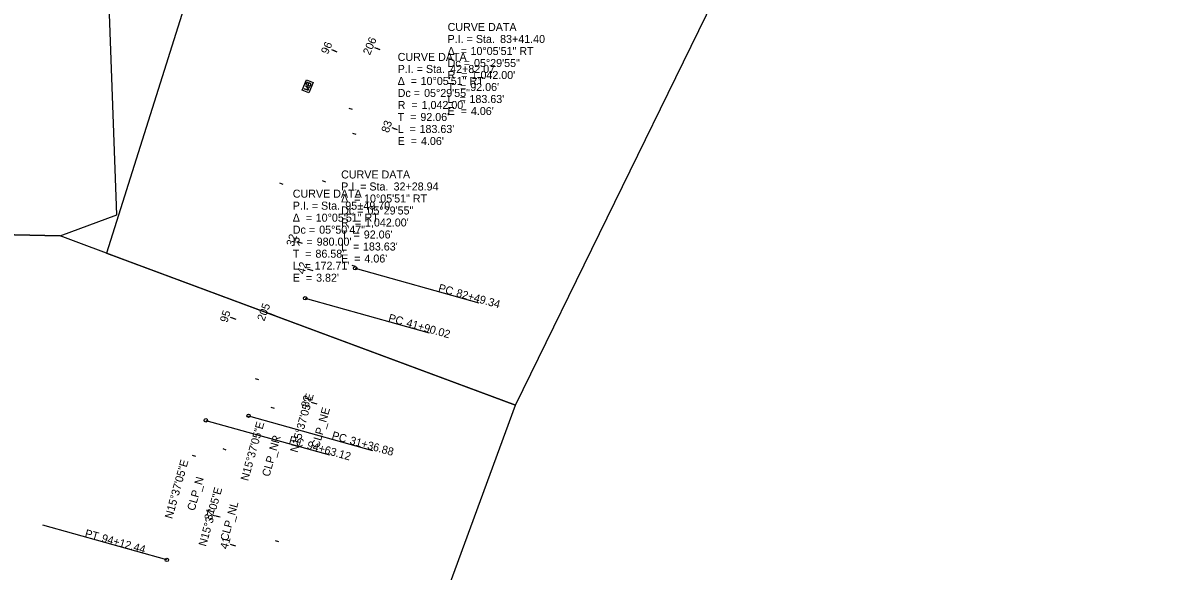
# Model space of a CAD drawing. Extents: x 1564517 to 1565226, y 635740 to 637455.
# Drawn here: x 1564828.9 to 1565225.9, y 636631.2 to 636823.1 of the extents above; entities that cross this region are included whole.
import ezdxf

# ---------------------------------------------------------------- set-up
doc = ezdxf.new("R2010")
doc.units = 0
for name, color, linetype in [('GK_Drainage_Nodes', 7, 'Continuous'), ('RD_P_Cells', 7, 'Continuous'), ('SC_Scratch10', 7, 'Continuous'), ('TX_P_1000', 7, 'Continuous'), ('UT_P_Water', 7, 'Continuous'), ('UT_P_Water_Cells', 7, 'Continuous'), ('UT_X_Electric', 7, 'Continuous'), ('UT_X_Sanitary_Pressure_Line', 7, 'Continuous'), ('UT_X_Water_Cells', 7, 'Continuous')]:
    doc.layers.add(name, color=color, linetype=linetype)

msp = doc.modelspace()

# ---------------------------------------------------------------- linework, layer by layer
at = {"layer": 'RD_P_Cells'}
msp.add_line((1564928.62, 636800.87), (1564928.62, 636800.87), dxfattribs=at)
msp.add_lwpolyline([(1564926.73, 636799.48), (1564928.25, 636803.19), (1564930.51, 636802.26), (1564928.99, 636798.56)], close=True, dxfattribs=at)
for points in [[(1564928.87, 636799.37), (1564927.39, 636799.98), (1564929.09, 636799.91), (1564927.82, 636801.03), (1564929.3, 636800.42)], [(1564928.94, 636801.84), (1564928.91, 636801.93), (1564928.89, 636801.98), (1564928.86, 636802.01), (1564928.84, 636802.03), (1564928.81, 636802.08), (1564928.78, 636802.1), (1564928.7, 636802.16), (1564928.67, 636802.17), (1564928.62, 636802.19), (1564928.55, 636802.21), (1564928.48, 636802.21), (1564928.42, 636802.19), (1564928.35, 636802.16), (1564928.31, 636802.12), (1564928.28, 636802.1), (1564928.24, 636802.05), (1564928, 636801.48), (1564929.48, 636800.87), (1564929.75, 636801.52), (1564929.73, 636801.62), (1564929.7, 636801.71), (1564929.63, 636801.81), (1564929.54, 636801.88), (1564929.44, 636801.94), (1564929.37, 636801.97), (1564929.29, 636801.97), (1564929.17, 636801.97), (1564929.08, 636801.94), (1564928.94, 636801.84), (1564928.68, 636801.2)]]:
    msp.add_lwpolyline(points, dxfattribs=at)
at = {"layer": 'TX_P_1000'}
for p, q in [((1564927.77, 636726.75), (1564971.11, 636714.64)), ((1564907.97, 636685.64), (1564951.31, 636673.53))]:
    msp.add_line(p, q, dxfattribs=at)
at = {"layer": 'UT_P_Water_Cells'}
for p, q in [((1564938.91, 636812.87), (1564937.81, 636813.35)), ((1564954.03, 636813.6), (1564952.93, 636814.07)), ((1564960.06, 636785.67), (1564958.92, 636786.05)), ((1564926.8, 636745.88), (1564925.66, 636746.27)), ((1564930.51, 636736.36), (1564929.35, 636736.69)), ((1564945.24, 636737.24), (1564988.58, 636725.12)), ((1564927.77, 636726.75), (1564971.11, 636714.64)), ((1564903.58, 636719.36), (1564901.68, 636719.97)), ((1564916.98, 636720.72), (1564915.11, 636721.42)), ((1564931.95, 636689.72), (1564930.8, 636690.04)), ((1564892.99, 636684.04), (1564936.33, 636671.92)), ((1564907.97, 636685.64), (1564951.31, 636673.53)), ((1564898.04, 636650.12), (1564896.89, 636650.45)), ((1564879.34, 636635.23), (1564836, 636647.34)), ((1564903.54, 636640.06), (1564902.38, 636640.38))]:
    msp.add_line(p, q, dxfattribs=at)
for centre in [(1564945.24, 636737.24), (1564927.77, 636726.75), (1564892.99, 636684.04), (1564907.97, 636685.64), (1564879.34, 636635.23)]:
    msp.add_circle(centre, 0.6, dxfattribs=at)
at = {"layer": 'UT_X_Electric'}
for points in [[(1564682.06, 636752.05), (1564842.01, 636748.56), (1564861.83, 636755.87), (1564842.73, 637279.63), (1564517.04, 637293.63), (1564662.12, 636876.82)], [(1564858.24, 636742.53), (1565001.39, 636689.39), (1565225.94, 637148.15), (1565017.94, 637248.32)], [(1564685.49, 636222.38), (1564930.72, 636197.15), (1564955.53, 636388.56), (1565013.42, 636482), (1565045.03, 636594.7), (1564968.04, 636598.47), (1565001.39, 636689.39), (1564864.83, 636740.08), (1564842.01, 636748.56), (1564682.06, 636752.05), (1564649.71, 636425.72), (1564708.41, 636418.15)]]:
    msp.add_lwpolyline(points, close=True, dxfattribs=at)
at = {"layer": 'UT_X_Sanitary_Pressure_Line'}
for p, q in [((1564945.24, 636737.24), (1564988.58, 636725.12)), ((1564927.77, 636726.75), (1564971.11, 636714.64)), ((1564903.58, 636719.36), (1564902.44, 636719.73)), ((1564916.98, 636720.72), (1564915.86, 636721.14)), ((1564892.99, 636684.04), (1564936.33, 636671.92)), ((1564907.97, 636685.64), (1564951.31, 636673.53)), ((1564879.34, 636635.23), (1564836, 636647.34))]:
    msp.add_line(p, q, dxfattribs=at)
for centre in [(1564945.24, 636737.24), (1564927.77, 636726.75), (1564892.99, 636684.04), (1564907.97, 636685.64), (1564879.34, 636635.23)]:
    msp.add_circle(centre, 0.6, dxfattribs=at)
at = {"layer": 'UT_X_Water_Cells'}
for p, q in [((1564938.91, 636812.87), (1564937.08, 636813.67)), ((1564954.03, 636813.6), (1564952.19, 636814.38)), ((1564944.27, 636792.72), (1564943.16, 636793.17)), ((1564945.57, 636784.03), (1564944.44, 636784.42)), ((1564960.06, 636785.67), (1564958.16, 636786.31)), ((1564934.95, 636767.38), (1564933.83, 636767.83)), ((1564920.05, 636766.57), (1564918.93, 636766.99)), ((1564926.8, 636745.88), (1564924.91, 636746.53)), ((1564930.51, 636736.36), (1564928.58, 636736.91)), ((1564945.42, 636737.87), (1564944.26, 636738.2)), ((1564903.58, 636719.36), (1564901.68, 636719.97)), ((1564916.98, 636720.72), (1564915.11, 636721.42)), ((1564911.58, 636698.25), (1564910.43, 636698.59)), ((1564917, 636688.22), (1564915.84, 636688.54)), ((1564931.95, 636689.72), (1564930.03, 636690.26)), ((1564900.15, 636673.64), (1564899.01, 636674.04)), ((1564889.46, 636671.4), (1564888.3, 636671.73)), ((1564898.04, 636650.12), (1564896.12, 636650.66)), ((1564903.54, 636640.06), (1564901.61, 636640.6)), ((1564918.49, 636641.56), (1564917.34, 636641.89))]:
    msp.add_line(p, q, dxfattribs=at)
for centre in [(1564927.77, 636726.75), (1564907.97, 636685.64)]:
    msp.add_circle(centre, 0.6, dxfattribs=at)

# ---------------------------------------------------------------- texts
at = {"layer": 'GK_Drainage_Nodes'}
for s, p in [('CURVE DATA', (1564977.6, 636820.23)), ('P.I. = Sta. ', (1564977.6, 636816.03)), ('83+41.40', (1564995.97, 636816.03)), ('CURVE DATA', (1564960.13, 636809.75)), ('Δ  = ', (1564977.6, 636811.83)), ('10°05\'51" RT', (1564985.62, 636811.83)), ('P.I. = Sta. ', (1564960.13, 636805.55)), ('Dc = ', (1564977.6, 636807.63)), ('42+82.07', (1564978.5, 636805.55)), ('05°29\'55"', (1564986.84, 636807.63)), ('Δ  = ', (1564960.13, 636801.35)), ('10°05\'51" RT', (1564968.16, 636801.35)), ('R  = ', (1564977.6, 636803.43)), ("1,042.00'", (1564985.97, 636803.43)), ('Dc = ', (1564960.13, 636797.15)), ('05°29\'55"', (1564969.37, 636797.15)), ('T  = ', (1564977.6, 636799.23)), ("92.06'", (1564985.53, 636799.23)), ('R  = ', (1564960.13, 636792.95)), ("1,042.00'", (1564968.5, 636792.95)), ('L  = ', (1564977.6, 636795.03)), ("183.63'", (1564985.25, 636795.03)), ('T  = ', (1564960.13, 636788.75)), ("92.06'", (1564968.07, 636788.75)), ('E  = ', (1564977.6, 636790.83)), ("4.06'", (1564985.75, 636790.83)), ('L  = ', (1564960.13, 636784.55)), ("183.63'", (1564967.78, 636784.55)), ("4.06'", (1564968.29, 636780.35)), ('E  = ', (1564960.13, 636780.35)), ('CURVE DATA', (1564940.34, 636768.64)), ('CURVE DATA', (1564923.42, 636761.93)), ('P.I. = Sta. ', (1564940.34, 636764.44)), ('32+28.94', (1564958.7, 636764.44)), ('P.I. = Sta. ', (1564923.42, 636757.73)), ('Δ  = ', (1564940.34, 636760.24)), ('95+49.70', (1564941.79, 636757.73)), ('10°05\'51" RT', (1564948.36, 636760.24)), ('Δ  = ', (1564923.42, 636753.53)), ('10°05\'51" RT', (1564931.45, 636753.53)), ('Dc = ', (1564940.34, 636756.04)), ('05°29\'55"', (1564949.57, 636756.04)), ('Dc = ', (1564923.42, 636749.33)), ('05°50\'47"', (1564932.66, 636749.33)), ('R  = ', (1564940.34, 636751.84)), ("1,042.00'", (1564948.7, 636751.84)), ('R  = ', (1564923.42, 636745.13)), ("980.00'", (1564931.79, 636745.13)), ('T  = ', (1564940.34, 636747.64)), ("92.06'", (1564948.27, 636747.64)), ('T  = ', (1564923.42, 636740.93)), ("86.58'", (1564931.36, 636740.93)), ('L  = ', (1564940.34, 636743.44)), ("183.63'", (1564947.98, 636743.44)), ('L  = ', (1564923.42, 636736.73)), ("172.71'", (1564931.07, 636736.73)), ('E  = ', (1564940.34, 636739.24)), ("4.06'", (1564948.49, 636739.24)), ('E  = ', (1564923.42, 636732.53)), ("3.82'", (1564931.58, 636732.53))]:
    msp.add_text(s, height=2.8, dxfattribs=at).set_placement(p)
for s, p in [('N15°37\'05"E', (1564925.09, 636672.58)), ('CLP_NE', (1564932.57, 636674.1)), ('N15°37\'05"E', (1564907.78, 636662.66)), ('CLP_NR', (1564915.25, 636664.15)), ('N15°37\'05"E', (1564881.23, 636649.4)), ('CLP_N', (1564889.07, 636652.21)), ('N15°37\'05"E', (1564893.06, 636639.74)), ('CLP_NL', (1564900.65, 636641.62))]:
    msp.add_text(s, height=2.8, rotation=74.3818, dxfattribs=at).set_placement(p)
at = {"layer": 'SC_Scratch10'}
for s, p in [('CURVE DATA', (1564977.6, 636820.23)), ('P.I. = Sta. ', (1564977.6, 636816.03)), ('83+41.40', (1564995.97, 636816.03)), ('CURVE DATA', (1564960.13, 636809.75)), ('Δ  = ', (1564977.6, 636811.83)), ('10°05\'51" RT', (1564985.62, 636811.83)), ('P.I. = Sta. ', (1564960.13, 636805.55)), ('Dc = ', (1564977.6, 636807.63)), ('42+82.07', (1564978.5, 636805.55)), ('05°29\'55"', (1564986.84, 636807.63)), ('Δ  = ', (1564960.13, 636801.35)), ('10°05\'51" RT', (1564968.16, 636801.35)), ('R  = ', (1564977.6, 636803.43)), ("1,042.00'", (1564985.97, 636803.43)), ('Dc = ', (1564960.13, 636797.15)), ('05°29\'55"', (1564969.37, 636797.15)), ('T  = ', (1564977.6, 636799.23)), ("92.06'", (1564985.53, 636799.23)), ('R  = ', (1564960.13, 636792.95)), ("1,042.00'", (1564968.5, 636792.95)), ('L  = ', (1564977.6, 636795.03)), ("183.63'", (1564985.25, 636795.03)), ('T  = ', (1564960.13, 636788.75)), ("92.06'", (1564968.07, 636788.75)), ('E  = ', (1564977.6, 636790.83)), ("4.06'", (1564985.75, 636790.83)), ('L  = ', (1564960.13, 636784.55)), ("183.63'", (1564967.78, 636784.55)), ("4.06'", (1564968.29, 636780.35)), ('E  = ', (1564960.13, 636780.35)), ('CURVE DATA', (1564940.34, 636768.64)), ('CURVE DATA', (1564923.42, 636761.93)), ('P.I. = Sta. ', (1564940.34, 636764.44)), ('32+28.94', (1564958.7, 636764.44)), ('P.I. = Sta. ', (1564923.42, 636757.73)), ('Δ  = ', (1564940.34, 636760.24)), ('95+49.70', (1564941.79, 636757.73)), ('10°05\'51" RT', (1564948.36, 636760.24)), ('Δ  = ', (1564923.42, 636753.53)), ('10°05\'51" RT', (1564931.45, 636753.53)), ('Dc = ', (1564940.34, 636756.04)), ('05°29\'55"', (1564949.57, 636756.04)), ('Dc = ', (1564923.42, 636749.33)), ('05°50\'47"', (1564932.66, 636749.33)), ('R  = ', (1564940.34, 636751.84)), ("1,042.00'", (1564948.7, 636751.84)), ('R  = ', (1564923.42, 636745.13)), ("980.00'", (1564931.79, 636745.13)), ('T  = ', (1564940.34, 636747.64)), ("92.06'", (1564948.27, 636747.64)), ('T  = ', (1564923.42, 636740.93)), ("86.58'", (1564931.36, 636740.93)), ('L  = ', (1564940.34, 636743.44)), ("183.63'", (1564947.98, 636743.44)), ('L  = ', (1564923.42, 636736.73)), ("172.71'", (1564931.07, 636736.73)), ('E  = ', (1564940.34, 636739.24)), ("4.06'", (1564948.49, 636739.24)), ('E  = ', (1564923.42, 636732.53)), ("3.82'", (1564931.58, 636732.53))]:
    msp.add_text(s, height=2.8, dxfattribs=at).set_placement(p)
for s, p in [('N15°37\'05"E', (1564925.09, 636672.58)), ('CLP_NE', (1564932.57, 636674.1)), ('N15°37\'05"E', (1564907.78, 636662.66)), ('CLP_NR', (1564915.25, 636664.15)), ('N15°37\'05"E', (1564881.23, 636649.4)), ('CLP_N', (1564889.07, 636652.21)), ('N15°37\'05"E', (1564893.06, 636639.74)), ('CLP_NL', (1564900.65, 636641.62))]:
    msp.add_text(s, height=2.8, rotation=74.3818, dxfattribs=at).set_placement(p)
at = {"layer": 'UT_P_Water'}
for s, p in [('CURVE DATA', (1564977.6, 636820.23)), ('P.I. = Sta. ', (1564977.6, 636816.03)), ('83+41.40', (1564995.97, 636816.03)), ('CURVE DATA', (1564960.13, 636809.75)), ('Δ  = ', (1564977.6, 636811.83)), ('10°05\'51" RT', (1564985.62, 636811.83)), ('P.I. = Sta. ', (1564960.13, 636805.55)), ('Dc = ', (1564977.6, 636807.63)), ('42+82.07', (1564978.5, 636805.55)), ('05°29\'55"', (1564986.84, 636807.63)), ('Δ  = ', (1564960.13, 636801.35)), ('10°05\'51" RT', (1564968.16, 636801.35)), ('R  = ', (1564977.6, 636803.43)), ("1,042.00'", (1564985.97, 636803.43)), ('Dc = ', (1564960.13, 636797.15)), ('05°29\'55"', (1564969.37, 636797.15)), ('T  = ', (1564977.6, 636799.23)), ("92.06'", (1564985.53, 636799.23)), ('R  = ', (1564960.13, 636792.95)), ("1,042.00'", (1564968.5, 636792.95)), ('L  = ', (1564977.6, 636795.03)), ("183.63'", (1564985.25, 636795.03)), ('T  = ', (1564960.13, 636788.75)), ("92.06'", (1564968.07, 636788.75)), ('E  = ', (1564977.6, 636790.83)), ("4.06'", (1564985.75, 636790.83)), ('L  = ', (1564960.13, 636784.55)), ("183.63'", (1564967.78, 636784.55)), ("4.06'", (1564968.29, 636780.35)), ('E  = ', (1564960.13, 636780.35)), ('CURVE DATA', (1564940.34, 636768.64)), ('CURVE DATA', (1564923.42, 636761.93)), ('P.I. = Sta. ', (1564940.34, 636764.44)), ('32+28.94', (1564958.7, 636764.44)), ('P.I. = Sta. ', (1564923.42, 636757.73)), ('Δ  = ', (1564940.34, 636760.24)), ('95+49.70', (1564941.79, 636757.73)), ('10°05\'51" RT', (1564948.36, 636760.24)), ('Δ  = ', (1564923.42, 636753.53)), ('10°05\'51" RT', (1564931.45, 636753.53)), ('Dc = ', (1564940.34, 636756.04)), ('05°29\'55"', (1564949.57, 636756.04)), ('Dc = ', (1564923.42, 636749.33)), ('05°50\'47"', (1564932.66, 636749.33)), ('R  = ', (1564940.34, 636751.84)), ("1,042.00'", (1564948.7, 636751.84)), ('R  = ', (1564923.42, 636745.13)), ("980.00'", (1564931.79, 636745.13)), ('T  = ', (1564940.34, 636747.64)), ("92.06'", (1564948.27, 636747.64)), ('T  = ', (1564923.42, 636740.93)), ("86.58'", (1564931.36, 636740.93)), ('L  = ', (1564940.34, 636743.44)), ("183.63'", (1564947.98, 636743.44)), ('L  = ', (1564923.42, 636736.73)), ("172.71'", (1564931.07, 636736.73)), ('E  = ', (1564940.34, 636739.24)), ("4.06'", (1564948.49, 636739.24)), ('E  = ', (1564923.42, 636732.53)), ("3.82'", (1564931.58, 636732.53))]:
    msp.add_text(s, height=2.8, dxfattribs=at).set_placement(p)
for s, p in [('N15°37\'05"E', (1564925.09, 636672.58)), ('CLP_NE', (1564932.57, 636674.1)), ('N15°37\'05"E', (1564907.78, 636662.66)), ('CLP_NR', (1564915.25, 636664.15)), ('N15°37\'05"E', (1564881.23, 636649.4)), ('CLP_N', (1564889.07, 636652.21)), ('N15°37\'05"E', (1564893.06, 636639.74)), ('CLP_NL', (1564900.65, 636641.62))]:
    msp.add_text(s, height=2.8, rotation=74.3818, dxfattribs=at).set_placement(p)
at = {"layer": 'UT_P_Water_Cells'}
for s, rotation, p in [('PC', 344.3818, (1564974.13, 636729.16)), ('82+49.34', 344.3818, (1564980.41, 636727.4)), ('205', 69.633, (1564913.45, 636718.52)), ('95', 72.2255, (1564900.48, 636718.04)), ('PC', 344.3818, (1564956.66, 636718.68)), ('41+90.02', 344.3818, (1564962.94, 636716.92)), ('PC', 344.3818, (1564936.86, 636677.57)), ('PC', 344.3818, (1564921.88, 636675.96)), ('94+63.12', 344.3818, (1564928.16, 636674.2)), ('31+36.88', 344.3818, (1564943.15, 636675.81)), ('PT', 344.3818, (1564850.45, 636643.31)), ('94+12.44', 344.3818, (1564856.31, 636641.67))]:
    msp.add_text(s, height=2.8, rotation=rotation, dxfattribs=at).set_placement(p)
at = {"layer": 'UT_X_Sanitary_Pressure_Line'}
for s, p in [('PC', (1564974.13, 636729.16)), ('82+49.34', (1564980.41, 636727.4)), ('PC', (1564956.66, 636718.68)), ('41+90.02', (1564962.94, 636716.92)), ('PC', (1564936.86, 636677.57)), ('PC', (1564921.88, 636675.96)), ('94+63.12', (1564928.16, 636674.2)), ('31+36.88', (1564943.15, 636675.81)), ('PT', (1564850.45, 636643.31)), ('94+12.44', (1564856.31, 636641.67))]:
    msp.add_text(s, height=2.8, rotation=344.3818, dxfattribs=at).set_placement(p)
at = {"layer": 'UT_X_Water_Cells'}
for s, rotation, p in [('96', 66.379, (1564935.7, 636811.88)), ('206', 66.8724, (1564950.4, 636811.58)), ('83', 71.5962, (1564956.95, 636784.41)), ('32', 70.9112, (1564923.67, 636744.65)), ('42', 73.8328, (1564927.5, 636734.95)), ('205', 69.633, (1564913.45, 636718.52)), ('95', 72.2255, (1564900.48, 636718.04)), ('82', 74.3818, (1564928.91, 636688.3)), ('31', 74.3818, (1564895.04, 636648.86)), ('41', 74.3818, (1564900.58, 636638.78))]:
    msp.add_text(s, height=2.8, rotation=rotation, dxfattribs=at).set_placement(p)

doc.saveas('drawing.dxf')
